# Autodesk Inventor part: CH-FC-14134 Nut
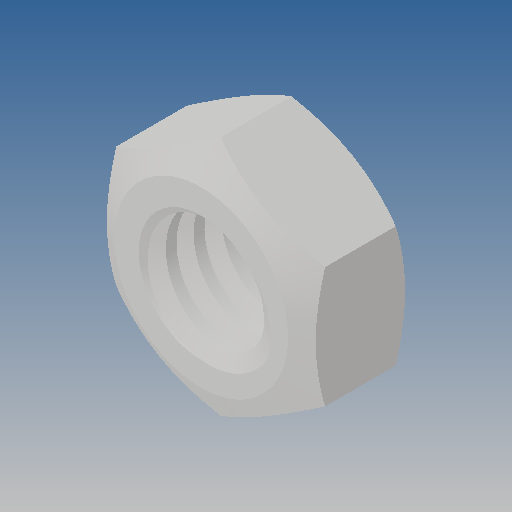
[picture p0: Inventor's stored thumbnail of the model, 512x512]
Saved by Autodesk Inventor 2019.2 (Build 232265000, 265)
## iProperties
Created: 2012-07
Part Number: CH-FC-14134 Nut
Material: Ogólny
Document SubType Name: Modeling
Designer: CADENGINEERING4
Density: 1 g/cm^3
Appearance: Domyślna
Author: CADENGINEERING4
Revision Number: ÈÎºÎ
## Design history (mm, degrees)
feature "ÇÐ³ý-É¨Ãè1"
node "Bryła1"
